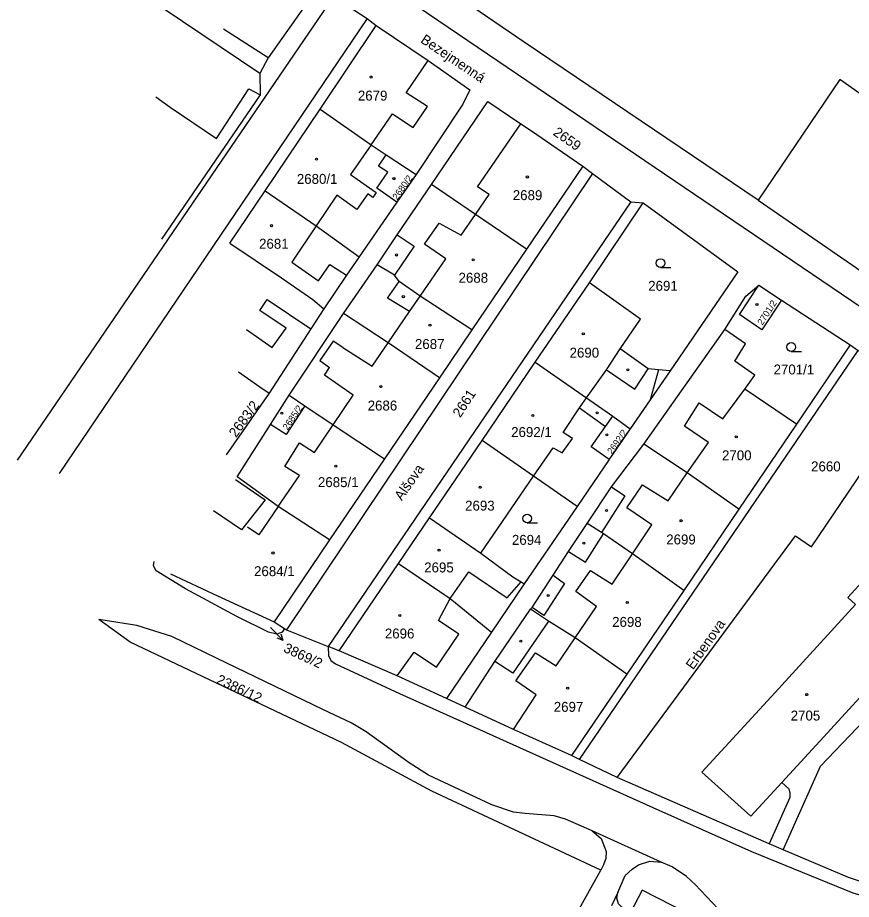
# Model space of a CAD drawing. Extents: x -527335 to -526256, y -1079142 to -1077836.
# Drawn here: x -527274.8 to -527132.2, y -1078877.1 to -1078726.1 of the extents above; entities that cross this region are included whole.
import ezdxf

# ---------------------------------------------------------------- set-up
doc = ezdxf.new("R2010")
doc.units = 0
for name, color, linetype in [('Hranice parcel', 7, 'Continuous'), ('Parcelní čísla', 7, 'Continuous'), ('Pop  PČ popisy', 7, 'Continuous'), ('Vnitřní kresba', 7, 'Continuous'), ('Značky budov', 7, 'Continuous'), ('Značky kultur', 7, 'Continuous')]:
    doc.layers.add(name, color=color, linetype=linetype)

msp = doc.modelspace()

# ---------------------------------------------------------------- linework, layer by layer
at = {"layer": 'Hranice parcel'}
for p, q in [((-527233.34, -1078735.68), (-527249.9, -1078724.58)), ((-527223.05, -1078741.81), (-527213.43, -1078727.51)), ((-527233.34, -1078735.68), (-527233.31, -1078739.33)), ((-527233.31, -1078739.33), (-527250.18, -1078764.05)), ((-527232.45, -1078755.79), (-527223.05, -1078741.81)), ((-527211.75, -1078749.6), (-527206.63, -1078753)), ((-527178.09, -1078751.58), (-527187.73, -1078765.8)), ((-527206.63, -1078753), (-527209.91, -1078757.75)), ((-527238.48, -1078764.75), (-527232.45, -1078755.79)), ((-527209.91, -1078757.75), (-527216.38, -1078767.11)), ((-527176.98, -1078771.52), (-527167.75, -1078757.84)), ((-527148.09, -1078757.41), (-527117.23, -1078778.72)), ((-527187.73, -1078765.8), (-527197.07, -1078779.59)), ((-527219.04, -1078776.77), (-527213.27, -1078768.45)), ((-527186.24, -1078785.14), (-527176.98, -1078771.52)), ((-527147.98, -1078771.96), (-527144.11, -1078774.49)), ((-527144.11, -1078774.49), (-527132.36, -1078782.16)), ((-527228.34, -1078790.78), (-527219.04, -1078776.77)), ((-527197.07, -1078779.59), (-527202.63, -1078787.79)), ((-527167.65, -1078799.14), (-527153.81, -1078779.52)), ((-527132.36, -1078782.16), (-527141.52, -1078795.74)), ((-527195.32, -1078798.51), (-527186.24, -1078785.14)), ((-527202.63, -1078787.79), (-527212.01, -1078801.64)), ((-527231.78, -1078790.42), (-527239.12, -1078800.95)), ((-527231.52, -1078795.76), (-527228.34, -1078790.78)), ((-527228.34, -1078790.78), (-527225.66, -1078792.58)), ((-527172.98, -1078794.38), (-527169.97, -1078796.5)), ((-527237.26, -1078804.76), (-527231.52, -1078795.76)), ((-527141.52, -1078795.74), (-527151.38, -1078810.26)), ((-527204.34, -1078811.78), (-527195.32, -1078798.51)), ((-527186.56, -1078804.61), (-527195.32, -1078798.51)), ((-527212.01, -1078801.64), (-527221.43, -1078815.54)), ((-527173.61, -1078801.8), (-527179.04, -1078809.84)), ((-527195.54, -1078817.79), (-527186.56, -1078804.61)), ((-527179.04, -1078809.84), (-527186.56, -1078804.61)), ((-527179.04, -1078809.84), (-527188.11, -1078823.03)), ((-527151.38, -1078810.26), (-527160.83, -1078824.19)), ((-527209.64, -1078819.58), (-527204.34, -1078811.78)), ((-527204.34, -1078811.78), (-527195.54, -1078817.79)), ((-527221.43, -1078815.54), (-527230.91, -1078829.53)), ((-527219.8, -1078834.53), (-527209.64, -1078819.58)), ((-527188.11, -1078823.03), (-527193.73, -1078831.31)), ((-527160.83, -1078824.19), (-527170.56, -1078838.53)), ((-527230.91, -1078829.53), (-527229.12, -1078830.72)), ((-527193.73, -1078831.31), (-527201.43, -1078842.66)), ((-527219.8, -1078834.53), (-527221.67, -1078833.78)), ((-527170.56, -1078838.53), (-527180.02, -1078852.46)), ((-527198.22, -1078844.16), (-527201.43, -1078842.66)), ((-527175.04, -1078872.05), (-527203.93, -1078858.55)), ((-527164.69, -1078870.72), (-527176.49, -1078865.35)), ((-527194.32, -1078906.65), (-527175.04, -1078872.05)), ((-527172.13, -1078875.88), (-527173.18, -1078878.19))]:
    msp.add_line(p, q, dxfattribs=at)
for points in [[(-527148.09, -1078757.41), (-527188.11, -1078730.34), (-527272.74, -1078672.59)], [(-527223.28, -1078720.72), (-527231.93, -1078733.05), (-527233.34, -1078735.68)], [(-527223.28, -1078720.72), (-527220.7, -1078722.5), (-527215.01, -1078726.29), (-527213.43, -1078727.51)], [(-527213.43, -1078727.51), (-527204.55, -1078733.5), (-527197.42, -1078738.48), (-527198.63, -1078740.94), (-527206.63, -1078753)], [(-527104.99, -1078757.3), (-527129.66, -1078739.88), (-527134.11, -1078736.73), (-527148.09, -1078757.41)], [(-527251.13, -1078739.72), (-527248.68, -1078741.47), (-527240.76, -1078746.83), (-527235.24, -1078738.32), (-527233.31, -1078739.33)], [(-527223.05, -1078741.81), (-527214.32, -1078747.89), (-527211.75, -1078749.6)], [(-527203.99, -1078754.68), (-527194.33, -1078740.49), (-527188.69, -1078744.31), (-527186.89, -1078745.53), (-527178.09, -1078751.58)], [(-527209.91, -1078757.75), (-527213.36, -1078755.36), (-527211.45, -1078752.61), (-527213.08, -1078751.59), (-527211.75, -1078749.6)], [(-527178.09, -1078751.58), (-527176.42, -1078752.82), (-527169.89, -1078757.67), (-527167.75, -1078757.84)], [(-527213.27, -1078768.45), (-527209.88, -1078763.32), (-527203.99, -1078754.68)], [(-527187.73, -1078765.8), (-527196.48, -1078759.82), (-527203.99, -1078754.68)], [(-527232.45, -1078755.79), (-527223.7, -1078761.76), (-527216.38, -1078767.11)], [(-527167.75, -1078757.84), (-527151.55, -1078769.65), (-527163.16, -1078786.58)], [(-527238.48, -1078764.75), (-527229.66, -1078770.66), (-527224.28, -1078774.41), (-527222.41, -1078775.99)], [(-527216.38, -1078767.11), (-527218.51, -1078770.25), (-527222.41, -1078775.99)], [(-527197.07, -1078779.59), (-527205.93, -1078773.79), (-527209.52, -1078771.33), (-527210.32, -1078770.24), (-527213.27, -1078768.45)], [(-527163.16, -1078786.58), (-527165.13, -1078786.44), (-527166.9, -1078786.25), (-527171.68, -1078782.84), (-527168.24, -1078777.73), (-527176.98, -1078771.52)], [(-527153.81, -1078779.52), (-527150.18, -1078773.8), (-527147.98, -1078771.96)], [(-527144.11, -1078774.49), (-527147.45, -1078779.6), (-527151.28, -1078776.95), (-527147.98, -1078771.96)], [(-527222.41, -1078775.99), (-527224.62, -1078779.4), (-527231.78, -1078790.42)], [(-527202.63, -1078787.79), (-527211.43, -1078781.81), (-527219.04, -1078776.77)], [(-527141.52, -1078795.74), (-527150.39, -1078789.76), (-527148.67, -1078787.33), (-527152.07, -1078784.94), (-527150.29, -1078781.95), (-527153.81, -1078779.52)], [(-527132.36, -1078782.16), (-527130.96, -1078783.09), (-527121.51, -1078787.51), (-527119.86, -1078788.49)], [(-527186.24, -1078785.14), (-527177.45, -1078791.24), (-527172.98, -1078794.38)], [(-527237.03, -1078786.79), (-527233.37, -1078789.32), (-527231.78, -1078790.42)], [(-527163.16, -1078786.58), (-527166.58, -1078791.56), (-527169.97, -1078796.5)], [(-527172.24, -1078856.19), (-527141.71, -1078814.86), (-527138.98, -1078816.71), (-527119.86, -1078788.49)], [(-527225.66, -1078792.58), (-527228.86, -1078797.51), (-527231.52, -1078795.76)], [(-527225.66, -1078792.58), (-527220.79, -1078795.84), (-527212.01, -1078801.64)], [(-527173.61, -1078801.8), (-527176.66, -1078799.6), (-527174.2, -1078796.11), (-527172.98, -1078794.38)], [(-527169.97, -1078796.5), (-527173.51, -1078801.65), (-527173.61, -1078801.8)], [(-527124.5, -1078833.07), (-527111.43, -1078818.8), (-527098.36, -1078804.54), (-527106.61, -1078796.85), (-527119.69, -1078811.12), (-527132.76, -1078825.39), (-527131.44, -1078826.61)], [(-527177.34, -1078812.71), (-527173.17, -1078806.44), (-527167.65, -1078799.14)], [(-527151.38, -1078810.26), (-527160.23, -1078804.08), (-527167.65, -1078799.14)], [(-527237.54, -1078805.17), (-527232.44, -1078808.69), (-527236.52, -1078813.83), (-527241.26, -1078810.57)], [(-527221.43, -1078815.54), (-527230.23, -1078809.82), (-527237.26, -1078804.76)], [(-527187.05, -1078827.41), (-527186.76, -1078827.13), (-527183.17, -1078821.58), (-527180.53, -1078817.5), (-527177.34, -1078812.71)], [(-527160.83, -1078824.19), (-527169.6, -1078817.93), (-527174.56, -1078814.49), (-527174.9, -1078814.27), (-527177.34, -1078812.71)], [(-527080.64, -1078811.86), (-527087.81, -1078822.05), (-527107.3, -1078857.78), (-527109.58, -1078856.49), (-527120.15, -1078874.63), (-527121.91, -1078875.54), (-527123.9, -1078875.45), (-527128.65, -1078874.62), (-527132.64, -1078873.34), (-527143.8, -1078868.59), (-527146.2, -1078867.57), (-527172.24, -1078856.19)], [(-527195.54, -1078817.79), (-527190.05, -1078821.88), (-527188.62, -1078822.73), (-527188.11, -1078823.03)], [(-527229.12, -1078830.72), (-527229.54, -1078831.32), (-527230.45, -1078831.68), (-527231.89, -1078831.31), (-527237.28, -1078828.66), (-527246.08, -1078823.92), (-527251.09, -1078820.81), (-527251.58, -1078819.97), (-527251.45, -1078819.23)], [(-527209.64, -1078819.58), (-527200.82, -1078825.55), (-527193.73, -1078831.31)], [(-527248.65, -1078821.32), (-527240.62, -1078825.12), (-527230.91, -1078829.53)], [(-527198.22, -1078844.16), (-527193.14, -1078836.36), (-527187.05, -1078827.41)], [(-527170.56, -1078838.53), (-527179.42, -1078832.29), (-527183.99, -1078829.42), (-527187.05, -1078827.41)], [(-527131.44, -1078826.61), (-527144.07, -1078840.4), (-527144.58, -1078840.95), (-527157.72, -1078855.29), (-527149.33, -1078862.84), (-527144.03, -1078857.05), (-527136.25, -1078848.56), (-527135.69, -1078847.95), (-527123.17, -1078834.29), (-527124.5, -1078833.07)], [(-527203.93, -1078858.55), (-527219.38, -1078850.21), (-527255.57, -1078833.02), (-527260.88, -1078829.16)], [(-527176.49, -1078865.35), (-527181.05, -1078863.31), (-527183, -1078862.75), (-527187.97, -1078862.36), (-527189.97, -1078862.11), (-527193.66, -1078860.86), (-527204.52, -1078855.8), (-527207.83, -1078853.68), (-527215.18, -1078848.39), (-527217.76, -1078846.84), (-527222.47, -1078844.62), (-527240.77, -1078835.8), (-527248.44, -1078832.06), (-527254.4, -1078830.16), (-527260.88, -1078829.16)], [(-527229.12, -1078830.72), (-527228.82, -1078830.92), (-527221.67, -1078833.78)], [(-527221.67, -1078833.78), (-527221.62, -1078835.3), (-527221.22, -1078836.2), (-527220.43, -1078836.77), (-527209.47, -1078841.8), (-527166.12, -1078861.35), (-527149.23, -1078868.84), (-527131.87, -1078875.96), (-527128.98, -1078876.81), (-527126.47, -1078877.28), (-527122.5, -1078877.6), (-527118.95, -1078877.18), (-527117.66, -1078876.76), (-527115.47, -1078875.73), (-527113.35, -1078874.31), (-527112.22, -1078872.94)], [(-527201.43, -1078842.66), (-527209.86, -1078838.81), (-527219.8, -1078834.53)], [(-527180.02, -1078852.46), (-527189.97, -1078848.01), (-527198.22, -1078844.16)], [(-527172.24, -1078856.19), (-527178.67, -1078853.11), (-527180.02, -1078852.46)], [(-527176.49, -1078865.35), (-527174.93, -1078866.65), (-527174.12, -1078868.87), (-527174.16, -1078870.05), (-527174.54, -1078871.14), (-527175.04, -1078872.05)], [(-527172.13, -1078875.88), (-527170.83, -1078873), (-527169.64, -1078871.89), (-527168.56, -1078871.14), (-527166.62, -1078870.55), (-527164.69, -1078870.72)], [(-527131.27, -1078905.61), (-527129.98, -1078902.76), (-527129.57, -1078900.28), (-527129.75, -1078897.92), (-527130.37, -1078895.67), (-527131.73, -1078893.14), (-527133.16, -1078891.42), (-527135.62, -1078889.51), (-527138.28, -1078888.1), (-527152.48, -1078880.73), (-527154.05, -1078879.64), (-527158.85, -1078874.52), (-527160.35, -1078873.17), (-527162.83, -1078871.49), (-527164.69, -1078870.72)], [(-527141.58, -1078888.96), (-527167.96, -1078875.51), (-527169.97, -1078879.4), (-527170.88, -1078878.9), (-527172, -1078877.81), (-527172.3, -1078876.87), (-527172.13, -1078875.88)]]:
    msp.add_lwpolyline(points, dxfattribs=at)
at = {"layer": 'Pop  PČ popisy'}
for p, q in [((-527231.53, -1078830.49), (-527231.45, -1078830.57)), ((-527231.45, -1078830.57), (-527229.36, -1078832.73)), ((-527229.36, -1078832.73), (-527230.42, -1078832.36)), ((-527229.36, -1078832.73), (-527229.7, -1078831.66))]:
    msp.add_line(p, q, dxfattribs=at)
at = {"layer": 'Vnitřní kresba'}
for p, q in [((-527274.8, -1078801.86), (-527220.7, -1078722.5)), ((-527206.11, -1078724.43), (-527130.49, -1078775.7)), ((-527215.01, -1078726.29), (-527267.67, -1078804.16)), ((-527231.93, -1078733.05), (-527239.55, -1078728.14)), ((-527208.34, -1078739.03), (-527204.55, -1078733.5)), ((-527204.65, -1078741.34), (-527208.34, -1078739.03)), ((-527207.12, -1078744.94), (-527204.65, -1078741.34)), ((-527214.32, -1078747.89), (-527210.67, -1078742.62)), ((-527210.67, -1078742.62), (-527207.12, -1078744.94)), ((-527196.12, -1078755.11), (-527188.69, -1078744.31)), ((-527214.32, -1078747.89), (-527217.85, -1078752.99)), ((-527176.42, -1078752.82), (-527228.82, -1078830.92)), ((-527217.85, -1078752.99), (-527213.44, -1078756.07)), ((-527194.13, -1078756.4), (-527196.12, -1078755.11)), ((-527220.18, -1078756.53), (-527223.7, -1078761.76)), ((-527216.76, -1078758.96), (-527220.18, -1078756.53)), ((-527214.86, -1078756.32), (-527216.76, -1078758.96)), ((-527214.04, -1078756.91), (-527214.86, -1078756.32)), ((-527213.44, -1078756.07), (-527214.04, -1078756.91)), ((-527196.48, -1078759.82), (-527194.13, -1078756.4)), ((-527169.89, -1078757.67), (-527221.67, -1078833.78)), ((-527198.91, -1078763.36), (-527196.48, -1078759.82)), ((-527205.18, -1078764.92), (-527202.69, -1078761.3)), ((-527202.69, -1078761.3), (-527198.91, -1078763.36)), ((-527209.88, -1078763.32), (-527206.95, -1078765.25)), ((-527206.95, -1078765.25), (-527210.32, -1078770.24)), ((-527201.55, -1078767.41), (-527205.18, -1078764.92)), ((-527205.93, -1078773.79), (-527201.55, -1078767.41)), ((-527211.51, -1078774.16), (-527209.52, -1078771.33)), ((-527233.35, -1078776.25), (-527232.12, -1078774.38)), ((-527232.12, -1078774.38), (-527224.62, -1078779.4)), ((-527207.78, -1078776.46), (-527211.51, -1078774.16)), ((-527207.78, -1078776.46), (-527205.93, -1078773.79)), ((-527228.84, -1078779.32), (-527233.35, -1078776.25)), ((-527211.43, -1078781.81), (-527207.78, -1078776.46)), ((-527235.67, -1078779.5), (-527231.23, -1078782.59)), ((-527231.23, -1078782.59), (-527228.84, -1078779.32)), ((-527219.14, -1078782.6), (-527214.13, -1078785.78)), ((-527214.13, -1078785.78), (-527211.43, -1078781.81)), ((-527178.67, -1078853.11), (-527130.96, -1078783.09)), ((-527174.02, -1078786.43), (-527171.68, -1078782.84)), ((-527222.31, -1078787.32), (-527221.42, -1078786)), ((-527177.45, -1078791.24), (-527174.02, -1078786.43)), ((-527174.02, -1078786.43), (-527169.2, -1078789.76)), ((-527169.2, -1078789.76), (-527166.9, -1078786.25)), ((-527165.13, -1078786.44), (-527166.58, -1078791.56)), ((-527217.39, -1078790.77), (-527222.31, -1078787.32)), ((-527154.12, -1078794.84), (-527150.39, -1078789.76)), ((-527220.79, -1078795.84), (-527217.39, -1078790.77)), ((-527178.66, -1078792.93), (-527177.45, -1078791.24)), ((-527181.45, -1078797.15), (-527178.66, -1078792.93)), ((-527178.66, -1078792.93), (-527174.2, -1078796.11)), ((-527160.72, -1078796.05), (-527158.19, -1078792.09)), ((-527158.19, -1078792.09), (-527154.12, -1078794.84)), ((-527223.98, -1078800.59), (-527220.79, -1078795.84)), ((-527156.61, -1078798.84), (-527160.72, -1078796.05)), ((-527179.87, -1078798.2), (-527181.45, -1078797.15)), ((-527229.08, -1078802.96), (-527226.55, -1078798.92)), ((-527226.55, -1078798.92), (-527223.98, -1078800.59)), ((-527181.62, -1078800.61), (-527179.87, -1078798.2)), ((-527160.23, -1078804.08), (-527156.61, -1078798.84)), ((-527186.56, -1078804.61), (-527183.16, -1078799.79)), ((-527183.16, -1078799.79), (-527181.62, -1078800.61)), ((-527226.6, -1078804.51), (-527229.08, -1078802.96)), ((-527230.23, -1078809.82), (-527226.6, -1078804.51)), ((-527163.52, -1078808.86), (-527160.23, -1078804.08)), ((-527173.17, -1078806.44), (-527170.9, -1078807.99)), ((-527170.55, -1078810.02), (-527167.88, -1078806.12)), ((-527167.88, -1078806.12), (-527163.52, -1078808.86)), ((-527170.9, -1078807.99), (-527174.9, -1078814.27)), ((-527230.23, -1078809.82), (-527233.53, -1078814.64)), ((-527166.27, -1078812.94), (-527170.55, -1078810.02)), ((-527233.53, -1078814.64), (-527235.48, -1078813.37)), ((-527169.6, -1078817.93), (-527166.27, -1078812.94)), ((-527177.66, -1078819.36), (-527174.56, -1078814.49)), ((-527180.53, -1078817.5), (-527177.66, -1078819.36)), ((-527173.07, -1078823.13), (-527169.6, -1078817.93)), ((-527200.82, -1078825.55), (-527197.59, -1078820.98)), ((-527197.59, -1078820.98), (-527191.07, -1078825.46)), ((-527183.17, -1078821.58), (-527181.25, -1078822.97)), ((-527179.29, -1078824.38), (-527176.78, -1078820.8)), ((-527176.78, -1078820.8), (-527173.07, -1078823.13)), ((-527191.07, -1078825.46), (-527188.62, -1078822.73)), ((-527181.25, -1078822.97), (-527184.76, -1078828.45)), ((-527175.77, -1078826.92), (-527179.29, -1078824.38)), ((-527202.8, -1078829.33), (-527200.82, -1078825.55)), ((-527184.76, -1078828.45), (-527186.76, -1078827.13)), ((-527179.42, -1078832.29), (-527175.77, -1078826.92)), ((-527199.29, -1078831.66), (-527202.8, -1078829.33)), ((-527183.99, -1078829.42), (-527190.09, -1078838.34)), ((-527203.11, -1078837.34), (-527199.29, -1078831.66)), ((-527182.66, -1078837.07), (-527179.42, -1078832.29)), ((-527209.86, -1078838.81), (-527206.96, -1078834.74)), ((-527206.96, -1078834.74), (-527203.11, -1078837.34)), ((-527189.58, -1078839.67), (-527186.17, -1078834.89)), ((-527186.17, -1078834.89), (-527182.66, -1078837.07)), ((-527190.09, -1078838.34), (-527193.14, -1078836.36)), ((-527186.09, -1078842.05), (-527189.58, -1078839.67)), ((-527189.97, -1078848.01), (-527186.09, -1078842.05)), ((-527137.41, -1078854.29), (-527128.03, -1078844.4)), ((-527143.8, -1078868.59), (-527137.41, -1078854.29)), ((-527144.03, -1078857.05), (-527142.86, -1078858.17)), ((-527142.65, -1078859.61), (-527146.2, -1078867.57)), ((-527142.86, -1078858.17), (-527142.65, -1078858.88)), ((-527142.65, -1078858.88), (-527142.65, -1078859.61))]:
    msp.add_line(p, q, dxfattribs=at)
for points in [[(-527223.7, -1078761.76), (-527227.9, -1078767.99), (-527223.3, -1078771.2), (-527221.37, -1078768.37), (-527218.51, -1078770.25)], [(-527219.14, -1078782.6), (-527220.81, -1078781.54), (-527223.1, -1078784.81), (-527221.42, -1078786)]]:
    msp.add_lwpolyline(points, dxfattribs=at)
at = {"layer": 'Značky budov'}
for centre in [(-527214.32, -1078736.31), (-527223.65, -1078750.37), (-527210.41, -1078753.7), (-527187.59, -1078753.42), (-527231.35, -1078761.75), (-527209.96, -1078766.77), (-527196.85, -1078767.59), (-527208.81, -1078773.9), (-527148.3, -1078775.24), (-527204.25, -1078778.79), (-527178.01, -1078780.28), (-527170.4, -1078786.42), (-527212.64, -1078789.3), (-527229.58, -1078793.86), (-527186.64, -1078794.26), (-527175.65, -1078793.77), (-527174, -1078797.55), (-527151.84, -1078797.88), (-527220.35, -1078802.92), (-527195.67, -1078806.53), (-527174.06, -1078810.51), (-527161.29, -1078812.25), (-527202.7, -1078817.28), (-527177.91, -1078816.1), (-527231.11, -1078817.78), (-527184.02, -1078825.05), (-527170.49, -1078826.24), (-527209.41, -1078828.48), (-527188.7, -1078832.86), (-527180.69, -1078840.92), (-527139.79, -1078842.02)]:
    msp.add_circle(centre, 0.175, dxfattribs=at)
at = {"layer": 'Značky kultur'}
for p, q in [((-527164.81, -1078768.9), (-527163.06, -1078768.9)), ((-527142.43, -1078783.27), (-527140.68, -1078783.27)), ((-527187.63, -1078812.62), (-527185.88, -1078812.62))]:
    msp.add_line(p, q, dxfattribs=at)
for centre in [(-527164.81, -1078768.15), (-527142.43, -1078782.52), (-527187.63, -1078811.87)]:
    msp.add_circle(centre, 0.75, dxfattribs=at)

# ---------------------------------------------------------------- texts
at = {"layer": 'Parcelní čísla'}
for s, p in [('2679', (-527216.59, -1078740.34)), ('2680/1', (-527227.03, -1078754.6)), ('2689', (-527190.08, -1078757.38)), ('2681', (-527233.49, -1078765.7)), ('2688', (-527199.36, -1078771.52)), ('2691', (-527166.91, -1078772.9)), ('2687', (-527206.82, -1078782.86)), ('2690', (-527180.36, -1078784.34)), ('2701/1', (-527145.46, -1078787.22)), ('2686', (-527214.91, -1078793.39)), ('2692/1', (-527190.36, -1078797.93)), ('2700', (-527154.28, -1078801.91)), ('2660', (-527139.04, -1078803.81)), ('2685/1', (-527223.42, -1078806.5)), ('2693', (-527198.24, -1078810.52)), ('2694', (-527190.23, -1078816.38)), ('2699', (-527163.83, -1078816.31)), ('2684/1', (-527234.35, -1078821.74)), ('2695', (-527205.24, -1078821.1)), ('2698', (-527173.08, -1078830.42)), ('2696', (-527211.97, -1078832.41)), ('2697', (-527183.07, -1078844.96)), ('2705', (-527142.53, -1078846.45))]:
    msp.add_text(s, height=1.7, dxfattribs=at).set_placement(p)
for s, height, rotation, p in [('2659', 1.7, 325, (-527183.31, -1078746.13)), ('2680/2', 1.14, 55, (-527209.84, -1078757.44)), ('2701/2', 1.14, 57, (-527147.37, -1078778.89)), ('2661', 1.7, 57, (-527199.07, -1078794.73)), ('2683/2', 1.7, 54, (-527237.43, -1078798.13)), ('2685/2', 1.139, 56, (-527228.6, -1078796.83)), ('2692/2', 1.139, 55, (-527173.1, -1078800.97)), ('3869/2', 1.7, 335, (-527229.45, -1078834.63)), ('2386/12', 1.7, 335, (-527240.93, -1078840.02))]:
    msp.add_text(s, height=height, rotation=rotation, dxfattribs=at).set_placement(p)
at = {"layer": 'Pop  PČ popisy'}
for s, rotation, p in [('Bezejmenná', 326, (-527205.99, -1078730.3)), ('Alšova', 55, (-527209.08, -1078808.93)), ('Erbenova', 55, (-527159.22, -1078837.86))]:
    msp.add_text(s, height=1.7, rotation=rotation, dxfattribs=at).set_placement(p)

doc.saveas('drawing.dxf')
